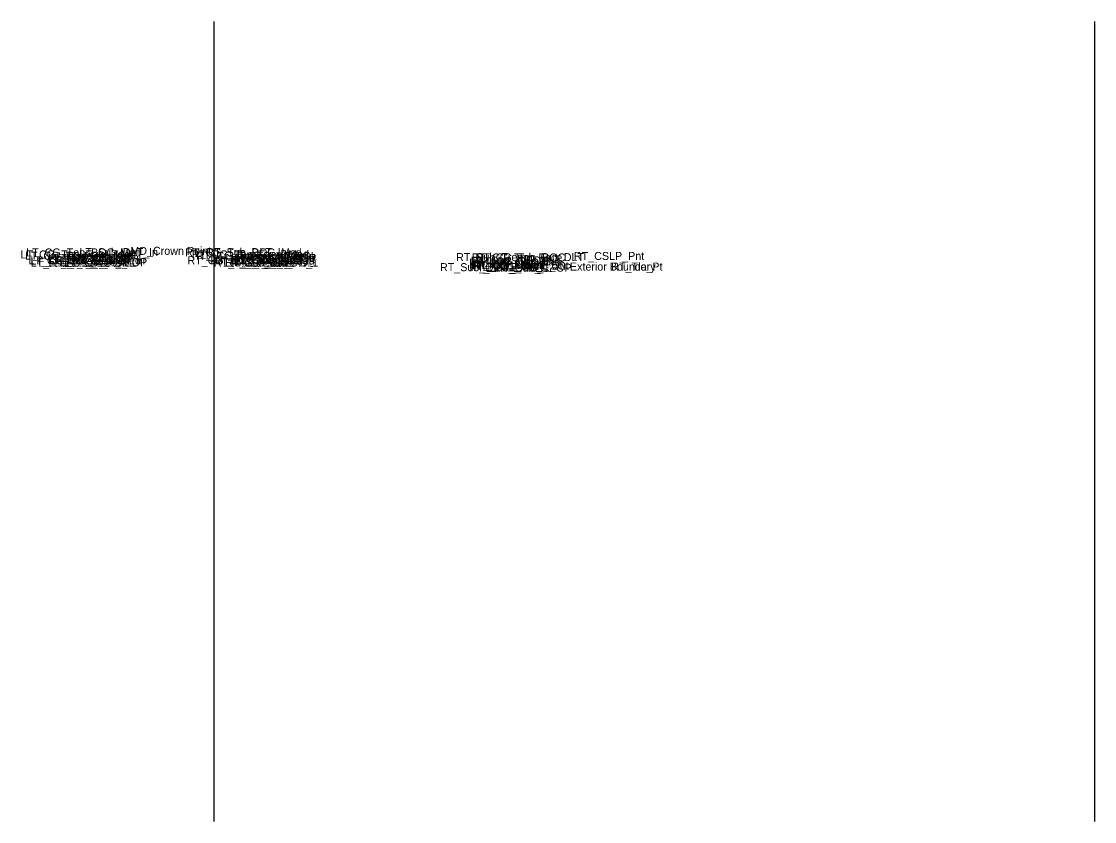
# Model space of a CAD drawing. Extents: x 0 to 6300, y -50 to 9550.
# Drawn here: x 2126 to 2260, y 5450 to 5550 of the extents above; entities that cross this region are included whole.
import ezdxf

# ---------------------------------------------------------------- set-up
doc = ezdxf.new("R2010")
doc.units = 0
for name, color, linetype in [('Default', 7, 'Continuous'), ('Prop XS Exc Vertical Line 2', 7, 'Continuous'), ('Prop XS Exc Vertical Line 3', 7, 'Continuous')]:
    doc.layers.add(name, color=color, linetype=linetype)

msp = doc.modelspace()

# ---------------------------------------------------------------- linework, layer by layer
at = {"layer": 'Prop XS Exc Vertical Line 2'}
msp.add_line((2150, 5550), (2150, 5450), dxfattribs=at)
at = {"layer": 'Prop XS Exc Vertical Line 3'}
msp.add_line((2260, 5550), (2260, 5450), dxfattribs=at)

# ---------------------------------------------------------------- texts
at = {"layer": 'Default'}
for s, p in [('MD_Crown Point', (2139.58, 5520.83)), ('LT_CG_Top_Face_Med', (2125.87, 5520.38)), ('LT_CG_Top_Gut_Med', (2126.42, 5520.22)), ('LT_CG_Top_BOC_Med', (2126.57, 5520.63)), ('LT_CG_Bot_BOC_Med', (2126.85, 5519.65)), ('LT_CG_Bot_IE_Med', (2127.09, 5519.62)), ('LT_PV2_OEEOP', (2129.29, 5519.95)), ('LT_PV3_OEEOP', (2129.29, 5519.7)), ('LT_PV2_IEEOP', (2130.05, 5519.95)), ('LT_CG1_Shelf_In', (2130.71, 5519.66)), ('LT_PV2_PGL', (2131.26, 5519.95)), ('LT_PV1_PGL', (2131.5, 5520.2)), ('LT_Sub_IEOP', (2133.05, 5519.41)), ('LT_Sub_DLT_In', (2133.22, 5520.67)), ('RT_CG_Top_BOC_Med', (2146.43, 5520.63)), ('RT_CG_Bot_BOC_Med', (2146.71, 5519.65)), ('RT_CG_Top_Face_Med', (2147.25, 5520.38)), ('RT_CG_Top_Gut_Med', (2147.8, 5520.22)), ('RT_Sub_DLT_In', (2149.07, 5520.67)), ('RT_CG1_Shelf_In', (2149.57, 5519.66)), ('RT_CG_Bot_IE_Med', (2149.98, 5519.62)), ('RT_Sub_IEOP', (2151.42, 5519.41)), ('RT_PV2_OEEOP', (2152.17, 5519.95)), ('RT_PV3_OEEOP', (2152.17, 5519.7)), ('RT_PV2_IEEOP', (2152.93, 5519.95)), ('RT_PV2_PGL', (2154.15, 5519.95)), ('RT_PV1_PGL', (2154.38, 5520.2)), ('RT_Sub_Trench_Out_DLT', (2180.26, 5520.04)), ('RT_PV1_OEOT', (2182.11, 5519.62)), ('RT_CG_Top_Face', (2182.22, 5520)), ('RT_CG_Top_BOC', (2182.69, 5520)), ('RT_CG_Top_Gut', (2182.75, 5519.5)), ('RT_CSLP_Pnt', (2194.98, 5520.19)), ('LT_Sub_IEOT_CG_1', (2127.13, 5519.37)), ('LT_Sub_OEEOP', (2129.33, 5519.33)), ('LT_Sub_IEEOP', (2130.09, 5519.33)), ('LT_Sub_PGL', (2131.31, 5519.33)), ('RT_Sub_IEOT_CG_1', (2150.01, 5519.37)), ('RT_Sub_OEEOP', (2152.21, 5519.33)), ('RT_Sub_IEEOP', (2152.97, 5519.33)), ('RT_Sub_PGL', (2154.19, 5519.33)), ('RT_Sub_OEOT_CG_1', (2178.25, 5518.79)), ('RT_PV2_OEOT', (2181.87, 5519.37)), ('RT_PV3_OEOT', (2181.87, 5519.12)), ('RT_Sub_OEOT', (2181.92, 5518.75)), ('RT_CG_Bot_IE', (2182.22, 5519.04)), ('RT_CG1_Shelf_Out', (2182.36, 5518.98)), ('RT_CG_Bot_BOC', (2182.97, 5518.99)), ('RT_Sub_OEOP', (2185.17, 5518.72)), ('Exterior Boundary', (2194.48, 5518.86)), ('RT_Tie_Pt', (2199.64, 5518.86))]:
    msp.add_text(s, height=1, dxfattribs=at).set_placement(p)

doc.saveas('drawing.dxf')
